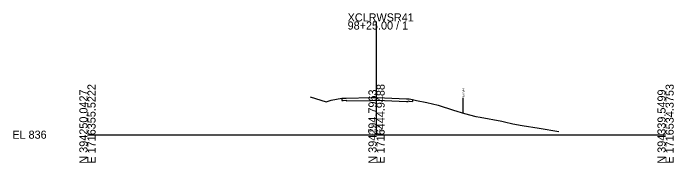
# Model space of a CAD drawing. Extents: x -26 to 1203, y -11 to 19524.
# Drawn here: x -25.7 to 202.8, y 4490.3 to 4541.9 of the extents above; entities that cross this region are included whole.
import ezdxf

# ---------------------------------------------------------------- set-up
doc = ezdxf.new("R2010")
doc.units = 0
for name, color, linetype in [('GK_Cells', 7, 'Continuous'), ('RW_X_Esmt_SH', 7, 'Continuous'), ('XS_P_Annotation', 7, 'Continuous'), ('XS_X_Ground_Line', 7, 'Continuous'), ('XS_X_Pavt', 7, 'Continuous')]:
    doc.layers.add(name, color=color, linetype=linetype)

msp = doc.modelspace()

# ---------------------------------------------------------------- linework, layer by layer
at = {"layer": 'GK_Cells'}
for p, q in [((100, 4500), (100, 4539.08)), ((0, 4500), (100, 4500)), ((100, 4500), (200, 4500))]:
    msp.add_line(p, q, dxfattribs=at)
at = {"layer": 'RW_X_Esmt_SH'}
msp.add_line((130, 4507.67), (130, 4512.67), dxfattribs=at)
at = {"layer": 'XS_X_Ground_Line'}
msp.add_lwpolyline([(77.05, 4513.03), (82.63, 4511.35), (84.31, 4511.88), (88.05, 4512.56), (88.49, 4512.59), (89.49, 4512.64), (98.12, 4512.84), (100.25, 4512.86), (110.41, 4512.42), (110.89, 4512.4), (111.3, 4512.33), (112.44, 4512.16), (113.78, 4511.85), (117.43, 4511.08), (121.37, 4510.2), (126.59, 4508.47), (130.42, 4507.29), (134.36, 4506.26), (135.9, 4505.99), (143.31, 4504.62), (144.26, 4504.44), (147.15, 4503.73), (150.34, 4503.13), (156.23, 4502.21), (163.07, 4501.13)], dxfattribs=at)
at = {"layer": 'XS_X_Pavt'}
for p, q in [((88.05, 4512.56), (88.05, 4511.81)), ((88.05, 4511.81), (88.49, 4511.84)), ((88.49, 4511.84), (89.49, 4511.89)), ((89.49, 4511.89), (89.49, 4511.64)), ((89.49, 4511.64), (98.12, 4511.84)), ((98.12, 4511.84), (100.25, 4511.86)), ((100.25, 4511.86), (110.41, 4511.42)), ((110.41, 4511.42), (110.89, 4511.4)), ((110.89, 4511.65), (111.3, 4511.58)), ((110.89, 4511.65), (110.89, 4511.4)), ((111.3, 4511.58), (112.44, 4511.41)), ((112.44, 4512.16), (112.44, 4511.41))]:
    msp.add_line(p, q, dxfattribs=at)

# ---------------------------------------------------------------- texts
at = {"layer": 'GK_Cells'}
for s, p in [('XCLRWSR41', (90, 4539.08)), ('98+25.00 / 1', (90, 4536.28)), ('EL 836', (-26, 4498.6))]:
    msp.add_text(s, height=2.8, dxfattribs=at).set_placement(p)
for s, p in [('E 1716355.5222', (2.8, 4490)), ('E 1716444.9488', (102.8, 4490)), ('E 1716534.3753', (202.8, 4490)), ('N 394250.0427', (0, 4490)), ('N 394294.7963', (100, 4490)), ('N 394339.5499', (200, 4490))]:
    msp.add_text(s, height=2.8, rotation=90, dxfattribs=at).set_placement(p)
at = {"layer": 'RW_X_Esmt_SH'}
msp.add_text('EX SH', height=0.7, rotation=90, dxfattribs=at).set_placement((130.35, 4513.02))
at = {"layer": 'XS_P_Annotation'}
for s, height, p in [('848.86', 0.7, (98.29, 4502.55)), ('98+25.00', 0.9, (96.94, 4501.05)), ('848.86', 0.7, (98.29, 4499.75))]:
    msp.add_text(s, height=height, dxfattribs=at).set_placement(p)

doc.saveas('drawing.dxf')
